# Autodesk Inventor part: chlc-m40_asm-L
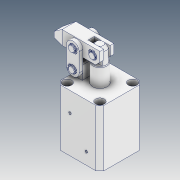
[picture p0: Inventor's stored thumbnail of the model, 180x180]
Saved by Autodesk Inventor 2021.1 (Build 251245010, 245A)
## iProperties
Created: 2019-11
Part Number: chlc-m40_asm-L
Material: Ogólny
Description: STEP AP214
Document SubType Name: Modeling
Designer: user
Density: 1 g/cm^3
Appearance: Domyślna
Company: Microsoft
Title: chlc-m40_asm-L.STEP
Author: Windows
Revision Number: ÈÎºÎ
Sending System: SolidWorks 2015
Preprocessor: SwSTEP 2.0
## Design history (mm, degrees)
feature "CHLC-40-01-1-solid1"
feature "CHLC-40-03-1-solid1"
feature "CHLC-40-06-6-solid1"
feature "CHLC-40-04-2-solid1"
feature "CHLC-40-06-7-solid1"
feature "CHLC-40-06-5-solid1"
feature "CHLC-40-06-1-solid1"
feature "CHLC-40-06-4-solid1"
feature "CHLC-40-͹̨-1-solid1"
feature "CHLC-40-08-1-solid1"
feature "CHLC-40-02-1-solid1"
feature "CHLC-40-06-3-solid1"
feature "CHLC-40-03-2-solid1"
feature "CHLC-40-02-2-solid1"
feature "NONE"
node "Bryła1"
node "Bryła2"
node "Bryła3"
node "Bryła4"
node "Bryła5"
node "Bryła6"
node "Bryła7"
node "Bryła8"
node "Bryła9"
node "Bryła10"
node "Bryła11"
node "Bryła12"
node "Bryła13"
node "Bryła14"
node "Bryła15"
